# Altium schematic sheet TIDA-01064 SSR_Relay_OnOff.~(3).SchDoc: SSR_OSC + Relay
size 431 x 279 mm; Date: Not shown in title block; ApprovedBy: Not shown in title block; CheckedBy: Not shown in title block; Author: Not shown in title block; CompanyName: Not shown in title block; DrawnBy: Jarrod Krebs; Engineer: Not shown in title block; Organization: Not shown in title block; Address1: Not shown in title block; Address2: Not shown in title block; Address3: Not shown in title block; Address4: Not shown in title block; DocumentNumber: 1; Revision: Use project parameter SCH_Rev; SheetNumber: 2; SheetTotal: 3; PageSetup: Record=PageOptions¦CenterHorizontal=True¦CenterVertical=True¦PrintScale=0.62¦XCorrection=1.00¦YCorrection=1.00¦PrintKind=0¦BorderSize=5000000¦LeftOffset=0¦BottomOffset=0¦Orientation=2¦PaperLength=1000¦PaperWidth=1000¦Scale=100¦PaperSource=15¦PrintQuality=-3¦MediaType=1¦DitherType=10¦PrintScaleMode=1¦PaperKind=Letter¦PaperIndex=1
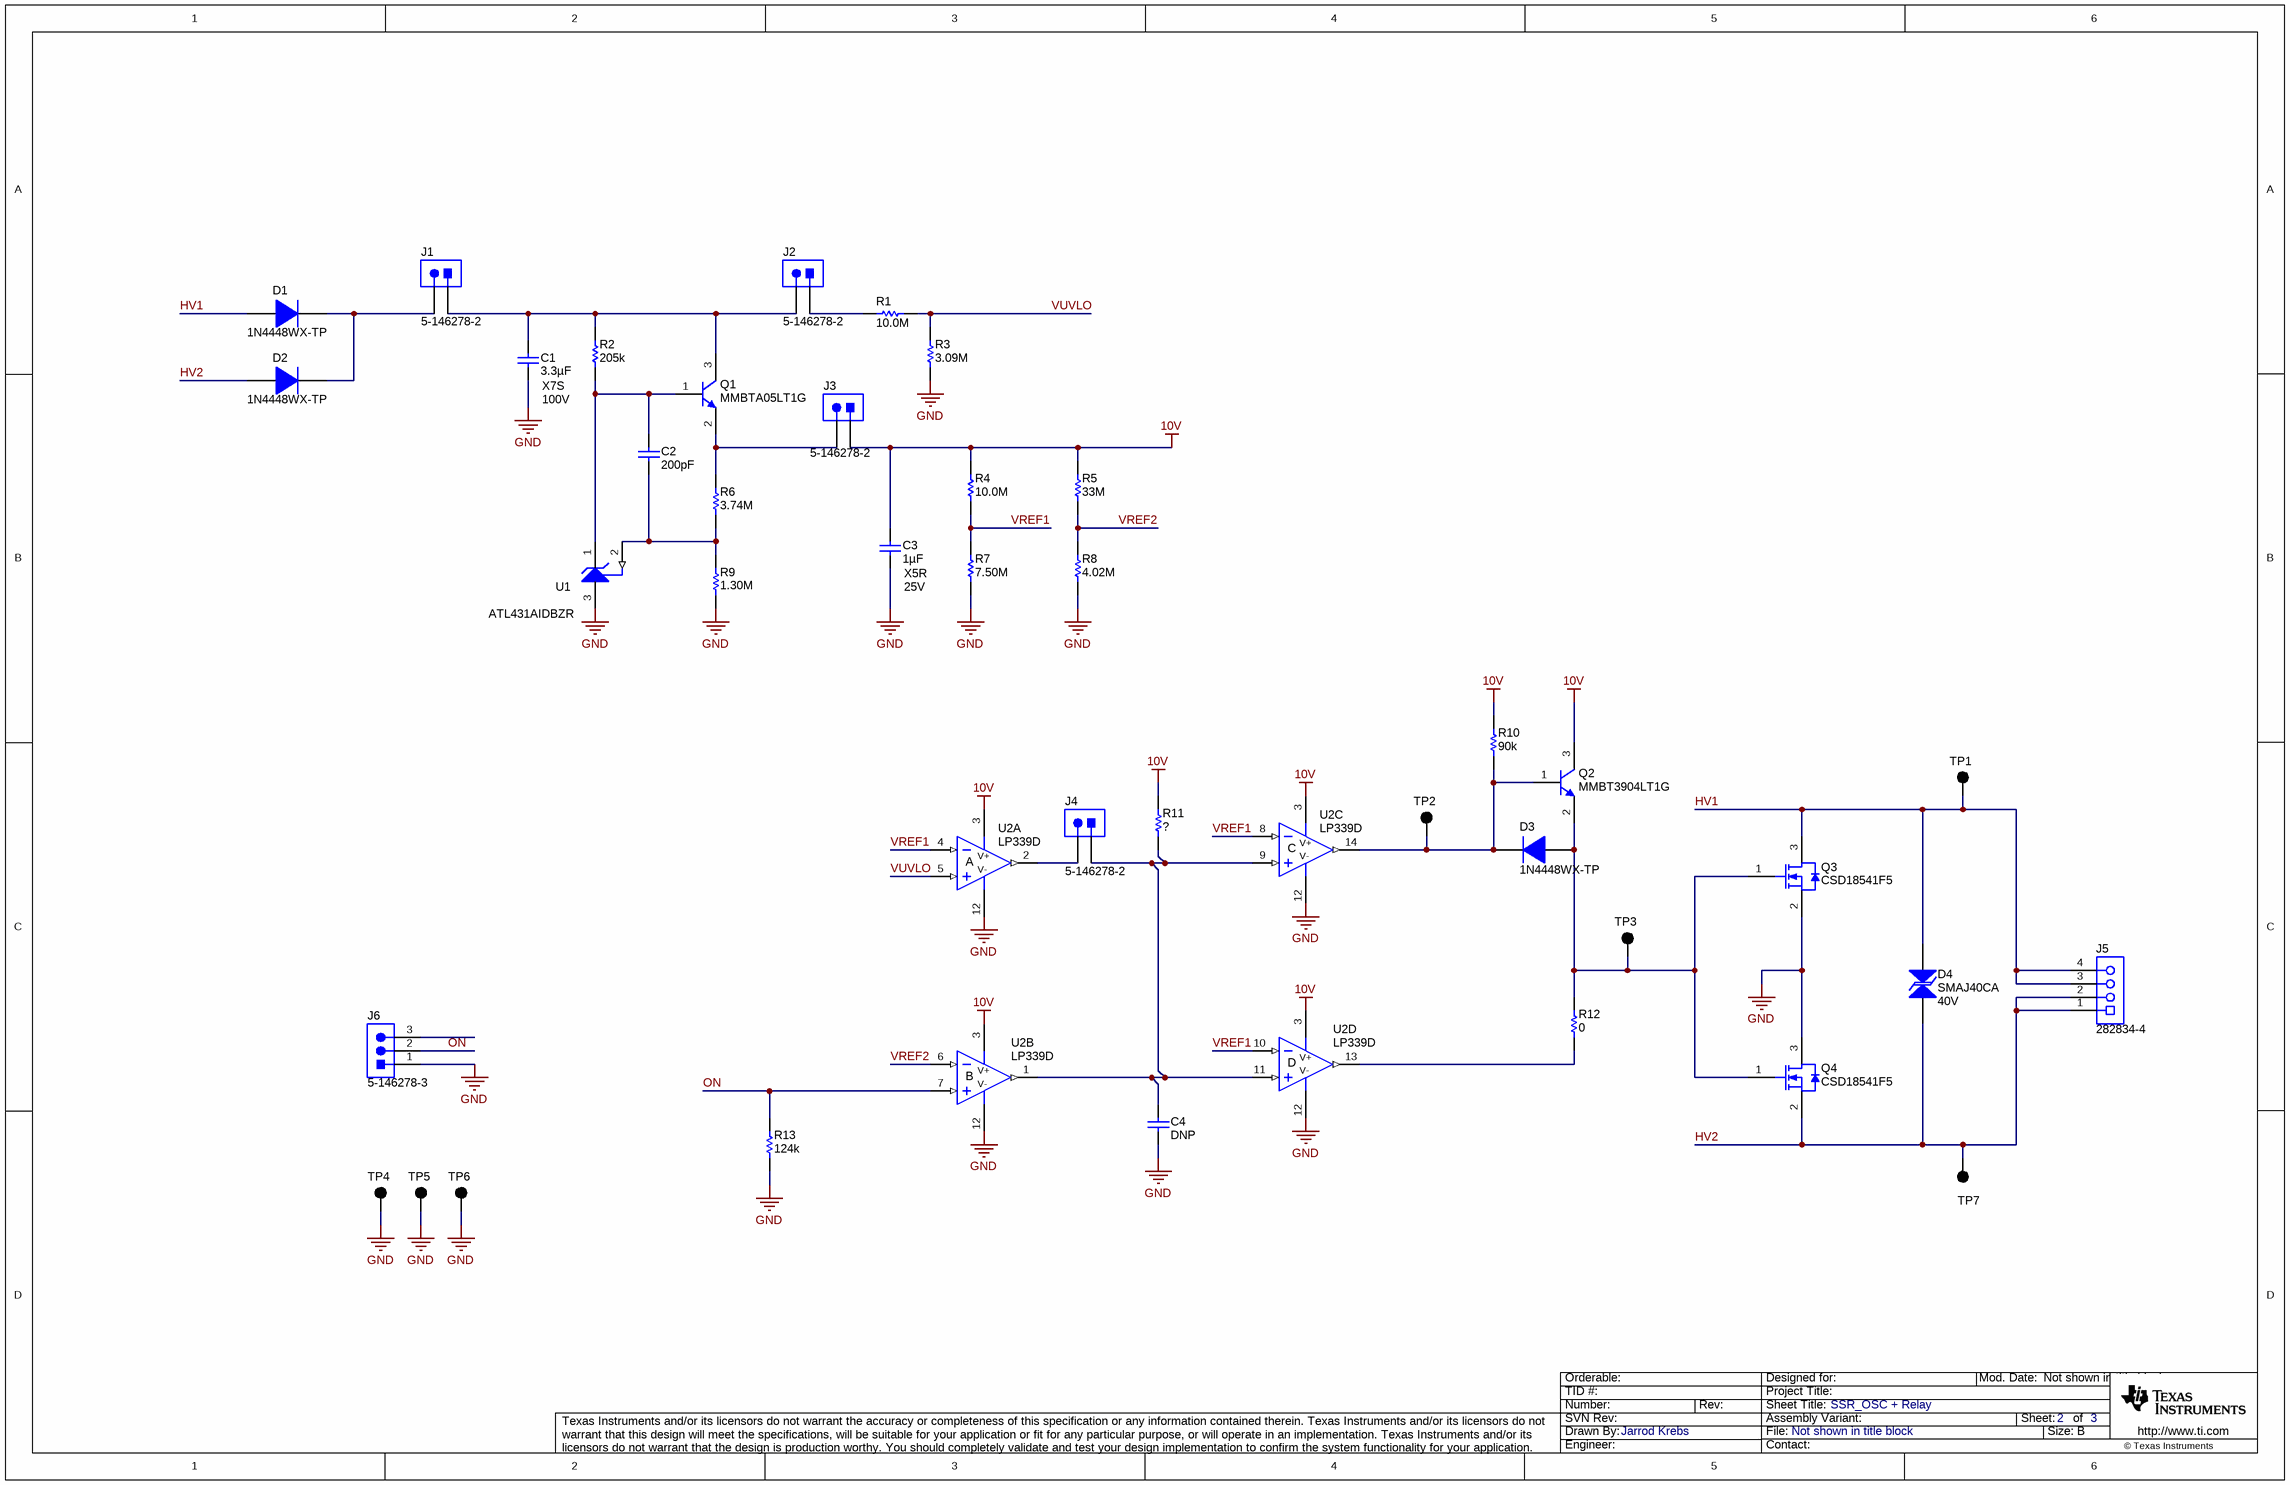
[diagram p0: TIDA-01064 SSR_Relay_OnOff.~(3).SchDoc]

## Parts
C1  ValueDisplayed: 3.3µF  Value2: 100V  TempCo: X7S  [1210]  (hidden comment: C3225X7S2A335M200AB)
C2  ValueDisplayed: 200pF  [0603]  (hidden comment: GRM1885C1H201JA01D)
C3  ValueDisplayed: 1µF  Value2: 25V  TempCo: X5R  [0603]  (hidden comment: GRM188R61E105KA12D)
C4  ValueDisplayed: DNP  [0603]  (hidden comment: GRM188R61E105KA12D)
D1  1N4448WX-TP  [sod-323]
D2  1N4448WX-TP  [sod-323]
D3  1N4448WX-TP  [sod-323]
D4  SMAJ40CA  value 40V  [SMA]
J1  5-146278-2  [TE_5-146278-2]
J2  5-146278-2  [TE_5-146278-2]
J3  5-146278-2  [TE_5-146278-2]
J4  5-146278-2  [TE_5-146278-2]
J5  282834-4  [TEC_282834-4]
J6  5-146278-3  [TE_5-146278-3]
Q1  MMBTA05LT1G  [SOT-23]
Q2  MMBT3904LT1G  [SOT-23]
Q3  CSD18541F5  [YJK0003A]
Q4  CSD18541F5  [YJK0003A]
R1  ValueDisplayed: 10.0M  [0805_HV]  (hidden comment: CRCW080510M0FKEA)
R2  ValueDisplayed: 205k  [0805_HV]  (hidden comment: CRCW0805205KFKEA)
R3  ValueDisplayed: 3.09M  [0805_HV]  (hidden comment: CRCW08053M09FKEA)
R4  ValueDisplayed: 10.0M  [0805_HV]  (hidden comment: CRCW080510M0FKEA)
R5  ValueDisplayed: 33M  [0805_HV]  (hidden comment: RC0805JR-0733ML)
R6  ValueDisplayed: 3.74M  [0805_HV]  (hidden comment: CRCW08053M74FKEA)
R7  ValueDisplayed: 7.50M  [0805_HV]  (hidden comment: CRCW08057M50FKEA)
R8  ValueDisplayed: 4.02M  [0805_HV]  (hidden comment: CRCW08054M02FKEA)
R9  ValueDisplayed: 1.30M  [0805_HV]  (hidden comment: CRCW08051M30FKEA)
R10  ValueDisplayed: 90k  [0805_HV]  (hidden comment: CRCW0805169KFKEA)
R11  CRCW0805402KFKEA  [0805_HV]  (value not drawn)
R12  ValueDisplayed: 0  [0805_HV]  (hidden comment: CRCW08050000Z0EA)
R13  ValueDisplayed: 124k  [0805_HV]  (hidden comment: CRCW0805124KFKEA)
TP1  5001  [Keystone5001]  (value not drawn)
TP2  5001  [Keystone5001]  (value not drawn)
TP3  5001  [Keystone5001]  (value not drawn)
TP4  5001  [Keystone5001]  (value not drawn)
TP5  5001  [Keystone5001]  (value not drawn)
TP6  5001  [Keystone5001]  (value not drawn)
TP7  5001  [Keystone5001]  (value not drawn)
U1  ATL431AIDBZR  [DBZ0003A_M]
U2  LP339D  [D0014A_N]  (parts A,B,C,D of 4)

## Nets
10V: C3.1 J3.1 Q2.3(C) R4.2 R5.2 R10.2 R11.2 U2.3(V+)
GND: C1.2 C3.2 C4.2 J6.1 Q3.2(S) Q4.3(D) R3.1 R7.1 R8.1 R9.1 R13.1 TP4.1 TP5.1 TP6.1 U1.3(ANODE) U2.12(V-)
HV1: D1.2(A) D4.2 J5.3 J5.4 Q3.3(D) TP1.1
HV2: D2.2(A) D4.1 J5.1 J5.2 Q4.2(S) TP7.1
ON: J6.2 R13.2 U2.7(+IN2)
VREF1: R4.1 R7.2 U2.4(-IN1) U2.8(-IN3) U2.10(-IN4)
VREF2: R5.1 R8.2 U2.6(-IN2)
VUVLO: R1.2 R3.2 U2.5(+IN1)
NetC1_1: C1.1 J1.1 J2.2 Q1.3(C) R2.2
NetC2_1: C2.1 Q1.1(B) R2.1 U1.1(CATHODE)
NetC2_2: C2.2 R6.1 R9.2 U1.2(REF)
NetC4_1: C4.1 J4.1 R11.1 U2.1(OUT2) U2.9(+IN3) U2.11(+IN4)
NetD1_1: D1.1(K) D2.1(K) J1.2
NetD3_1: D3.1(K) Q2.1(B) R10.1 TP2.1 U2.14(OUT3)
NetD3_2: D3.2(A) Q2.2(E) Q3.1(G) Q4.1(G) R12.2 TP3.1
NetJ2_1: J2.1 R1.1
NetJ3_2: J3.2 Q1.2(E) R6.2
NetJ4_2: J4.2 U2.2(OUT1)
NetR12_1: R12.1 U2.13(OUT4)

Not connected (* = marked no-connect by the designer): J6 3

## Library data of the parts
C1 = C3225X7S2A335M200AB: CAP, CERM, 3.3 µF, 100 V, +/- 20%, X7S, 1210; Manufacturer: TDK; Polarized: N; CompType: Capacitor; Value: 3.3uF; U/M: EA; Cap_F: 0.0000033; Tolerance_%: 20; Value1: Unknown; VDC_V: 100; TaMin_C: -55; TaMax_C: 125; AEC Category: Q200
C2 = GRM1885C1H201JA01D: CAP, CERM, 200 pF, 50 V, +/- 5%, C0G/NP0, 0603; Manufacturer: MuRata; Polarized: N; CompType: Capacitor; Value: 200pF; U/M: EA; Cap_F: 0.0000000002; Tolerance_%: 5; Value1: Unknown; VDC_V: 50; Value2: 50V; TaMin_C: -55; TaMax_C: 125; AEC Category: Q200
C3 = GRM188R61E105KA12D: CAP, CERM, 1 µF, 25 V, +/- 10%, X5R, 0603; Manufacturer: MuRata; Polarized: N; CompType: Capacitor; Value: 1uF; U/M: EA; Cap_F: 0.000001; Tolerance_%: 10; Value1: Unknown; VDC_V: 25; TaMin_C: -55; TaMax_C: 85; AEC Category: Q200
C4 = GRM188R61E105KA12D: CAP, CERM, 1 µF, 25 V, +/- 10%, X5R, 0603; Manufacturer: MuRata; Polarized: N; CompType: Capacitor; Value: 1uF; U/M: EA; Cap_F: 0.000001; Tolerance_%: 10; Value1: Unknown; VDC_V: 25; Value2: 25V; TaMin_C: -55; TaMax_C: 85; AEC Category: Q200
D1-D3 = 1N4448WX-TP: Diode, Switching, 75 V, 0.25 A, SOD-323; Manufacturer: Micro Commercial Components; U/M: EA; Value: 75V; Value1: 0.25A; Io_A: 0.25; Vr_V: 75; TJmax_C: 150; AEC Category: Q101
D4 = SMAJ40CA: Diode, TVS, Bi, 40 V, 400 W, SMA; Manufacturer: Littelfuse; U/M: EA; Power_W: 400; Vr_V: 40; Value1: 400W; RJA_CperW: 120; AEC Category: Q101
J1-J4 = 5-146278-2: Header, 100mil, 2x1, Tin, TH; Manufacturer: TE Connectivity; SymbolCreator: a0412235; U/M: EA
J5 = 282834-4: Terminal Block, 100mil, 4X1 TH; Manufacturer: TE Connectivity; SymbolCreator: a0411947
J6 = 5-146278-3: Header, 100mil, 3x1, Tin, TH; Manufacturer: TE Connectivity; SymbolCreator: a0799628
Q1 = MMBTA05LT1G, ON Semiconductor: Transistor, NPN, 60 V, 0.5 A, AEC-Q101, SOT-23; CompType: BJT; PNP: 0; NPN: 1; Vceo_V: 60; Vcesat1_V: 0.25; Value: 60 V; IcRated_A: 0.5; Value1: 0.5 A; TaMin_C: -55; TaMax_C: 150; U/M: EA; AEC Category: Q101; AEC Qualified: Y
Q2 = MMBT3904LT1G, ON Semiconductor: Transistor, NPN, 40 V, 0.2 A, SOT-23; CompType: BJT; PNP: 0; NPN: 1; Vceo_V: 40; Vcesat1_V: 0.3; Value: 40 V; IcRated_A: 0.2; Value1: 0.2 A; HfeMax: 300; TaMin_C: -55; TaMax_C: 150; U/M: EA; AEC Category: Q101
Q3 Q4 = CSD18541F5: MOSFET, N-CH, 60 V,  A, PICOSTAR-3; Manufacturer: Texas Instruments; Alternate Manufacturer: None; U/M: EA; ChType: N; Value: 60V; VdsMax_V: 60; Value1: 0.13 ohm; Rdson45_ohm: 0.13; Value2: 9.2 nC; QgTyp_nC: 9.2; Vgs_V: 20; AEC Category: Q101
R1 R4 = CRCW080510M0FKEA: RES, 10.0 M, 1%, 0.125 W, 0805; Manufacturer: Vishay-Dale; CompType: Resistor; Value: 10.0Meg; Res_ohm: 10000000; Value_Code: 10M0; Tolerance_%: 1; Power_W: 0.125; Value2: 0.125W; VDC_V: 150; TempCo: 100 ppm/C; EIA_Code: E96; U/M: EA; AEC Category: Q200
R2 = CRCW0805205KFKEA: RES, 205 k, 1%, 0.125 W, 0805; Manufacturer: Vishay-Dale; CompType: Resistor; Value: 205k; Res_ohm: 205000; Tolerance_%: 1; Power_W: 0.125; Value2: 0.125W; VDC_V: 150; TempCo: 100 ppm/C; EIA_Code: E96; U/M: EA; AEC Category: Q200
R3 = CRCW08053M09FKEA: RES, 3.09 M, 1%, 0.125 W, 0805; Manufacturer: Vishay-Dale; CompType: Resistor; Value: 3.09Meg; Res_ohm: 3090000; Value_Code: 3M09; Tolerance_%: 1; Power_W: 0.125; Value2: 0.125W; VDC_V: 150; TempCo: 100 ppm/C; EIA_Code: E96; U/M: EA; AEC Category: Q200
R5 = RC0805JR-0733ML: RES, 33 M, 5%, 0.125 W, 0805; Manufacturer: Yageo America; CompType: Resistor; Value: 33Meg; Res_ohm: 33000000; Value_Code: 33M0; Tolerance_%: 5; Power_W: 0.125; Value2: 0.125W; VDC_V: 150; TempCo: 300 ppm/C; U/M: EA; AEC Category: Q200; AEC Qualified: N
R6 = CRCW08053M74FKEA: RES, 3.74 M, 1%, 0.125 W, 0805; Manufacturer: Vishay-Dale; CompType: Resistor; Value: 3.74Meg; Res_ohm: 3740000; Value_Code: 3M74; Tolerance_%: 1; Power_W: 0.125; Value2: 0.125W; VDC_V: 150; TempCo: 100 ppm/C; EIA_Code: E96; U/M: EA; AEC Category: Q200
R7 = CRCW08057M50FKEA: RES, 7.50 M, 1%, 0.125 W, 0805; Manufacturer: Vishay-Dale; CompType: Resistor; Value: 7.50Meg; Res_ohm: 7500000; Value_Code: 7M50; Tolerance_%: 1; Power_W: 0.125; Value2: 0.125W; VDC_V: 150; TempCo: 100 ppm/C; EIA_Code: E96; U/M: EA; AEC Category: Q200
R8 = CRCW08054M02FKEA: RES, 4.02 M, 1%, 0.125 W, 0805; Manufacturer: Vishay-Dale; CompType: Resistor; Value: 4.02Meg; Res_ohm: 4020000; Value_Code: 4M02; Tolerance_%: 1; Power_W: 0.125; Value2: 0.125W; VDC_V: 150; TempCo: 100 ppm/C; EIA_Code: E96; U/M: EA; AEC Category: Q200
R9 = CRCW08051M30FKEA: RES, 1.30 M, 1%, 0.125 W, 0805; Manufacturer: Vishay-Dale; CompType: Resistor; Value: 1.30Meg; Res_ohm: 1300000; Value_Code: 1M30; Tolerance_%: 1; Power_W: 0.125; Value2: 0.125W; VDC_V: 150; TempCo: 100 ppm/C; EIA_Code: E96; U/M: EA; AEC Category: Q200
R10 = CRCW0805169KFKEA: RES, 169 k, 1%, 0.125 W, 0805; Manufacturer: Vishay-Dale; CompType: Resistor; Value: 169k; Res_ohm: 169000; Tolerance_%: 1; Power_W: 0.125; Value2: 0.125W; VDC_V: 150; TempCo: 100 ppm/C; EIA_Code: E96; U/M: EA; AEC Category: Q200
R11 = CRCW0805402KFKEA: RES, 402 k, 1%, 0.125 W, 0805; Manufacturer: Vishay-Dale; CompType: Resistor; Value: 402k; Res_ohm: 402000; Tolerance_%: 1; Power_W: 0.125; Value2: 0.125W; VDC_V: 150; TempCo: 100 ppm/C; EIA_Code: E96; U/M: EA; AEC Category: Q200
R12 = CRCW08050000Z0EA: RES, 0, 5%, 0.125 W, 0805; Manufacturer: Vishay-Dale; CompType: Resistor; Value: 0; Value_Code: 0000; Tolerance_%: 5; Power_W: 0.125; Value2: 0.125W; VDC_V: 150; TempCo: 200 ppm/C; EIA_Code: E24; U/M: EA; AEC Category: Q200
R13 = CRCW0805124KFKEA: RES, 124 k, 1%, 0.125 W, 0805; Manufacturer: Vishay-Dale; CompType: Resistor; Value: 124k; Res_ohm: 124000; Tolerance_%: 1; Power_W: 0.125; Value2: 0.125W; VDC_V: 150; TempCo: 100 ppm/C; EIA_Code: E96; U/M: EA; AEC Category: Q200
TP1-TP7 = 5001: Test Point, Miniature, Black, TH; Manufacturer: Keystone; CompType: Test Point Loop; U/M: EA
U1 = ATL431AIDBZR: 2.5V Low Iq Adjustable Precision Shunt Regulator, DBZ0003A; Manufacturer: Texas Instruments; SymbolCreator: a0412235; CompType: IC; U/M: EA
U2 = LP339D: Quad, Low-Power, General Purpose Differential Comparator, D0014A; Manufacturer: Texas Instruments; SymbolCreator: Altium; CompType: OpAmp IC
